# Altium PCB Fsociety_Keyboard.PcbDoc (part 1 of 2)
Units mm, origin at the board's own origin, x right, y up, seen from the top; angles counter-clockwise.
Board outline 368.7 x 110 mm, 2 copper layers (Top Layer, Bottom Layer), stack 1.601 mm thick; 249 components, 201 nets, 1088 pads, 275 vias.
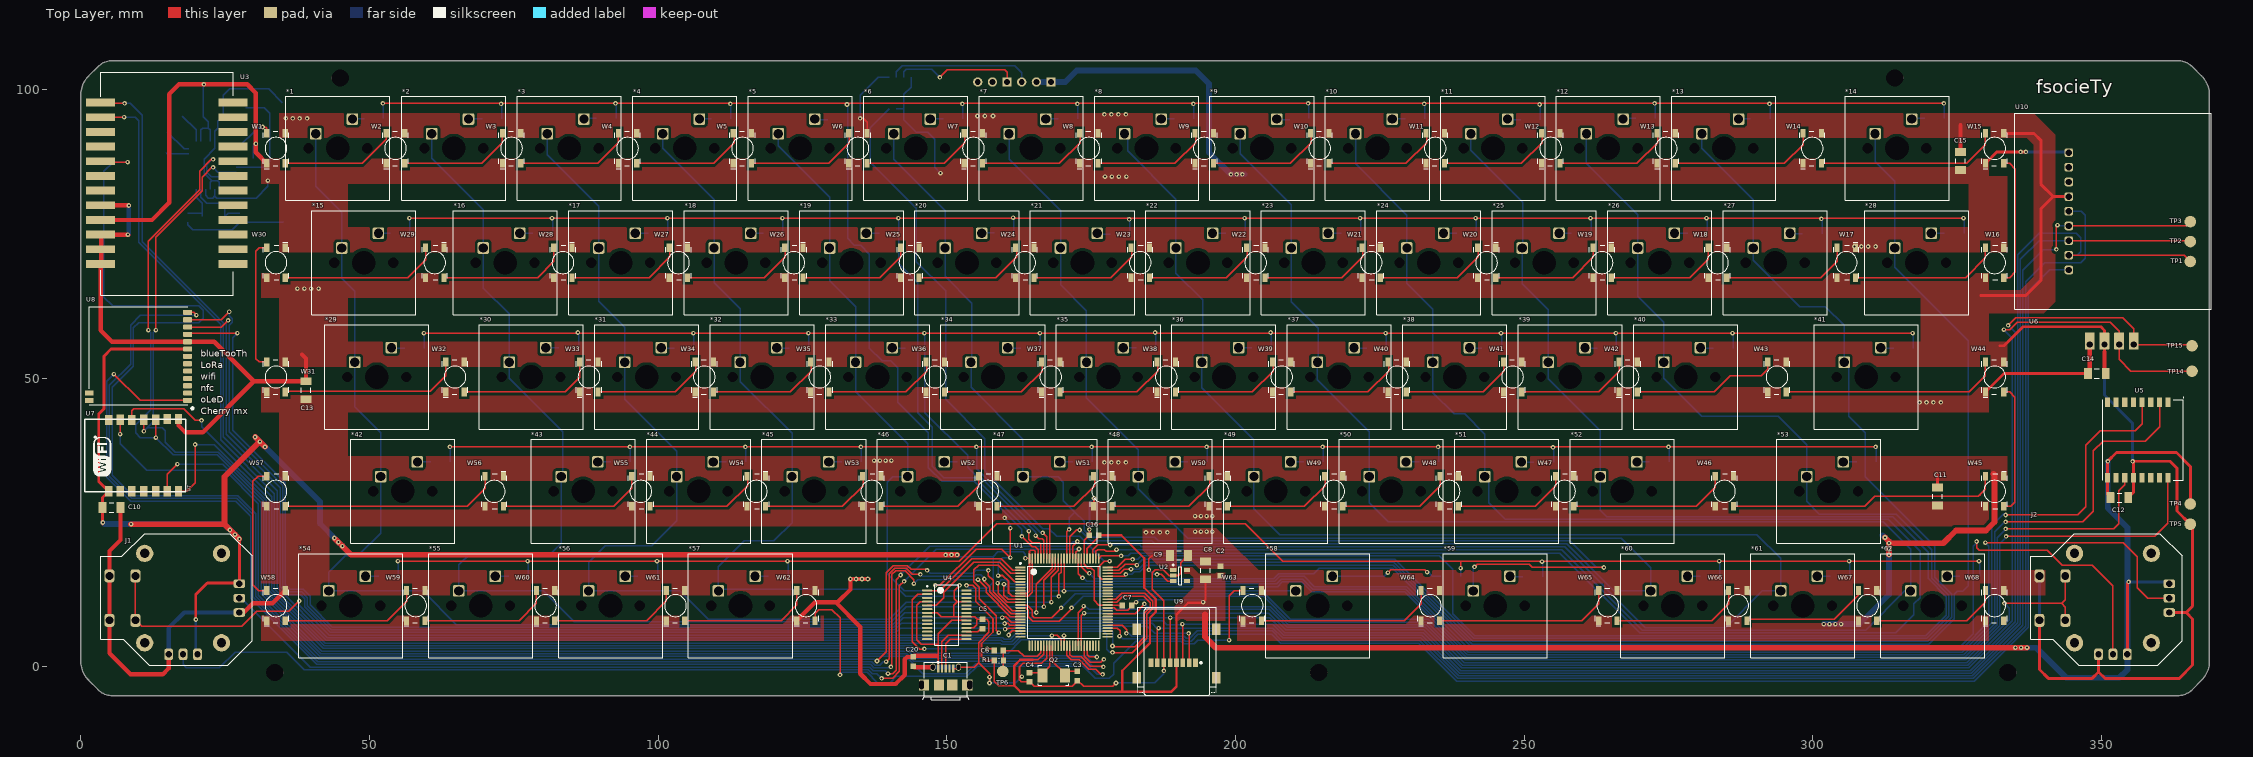
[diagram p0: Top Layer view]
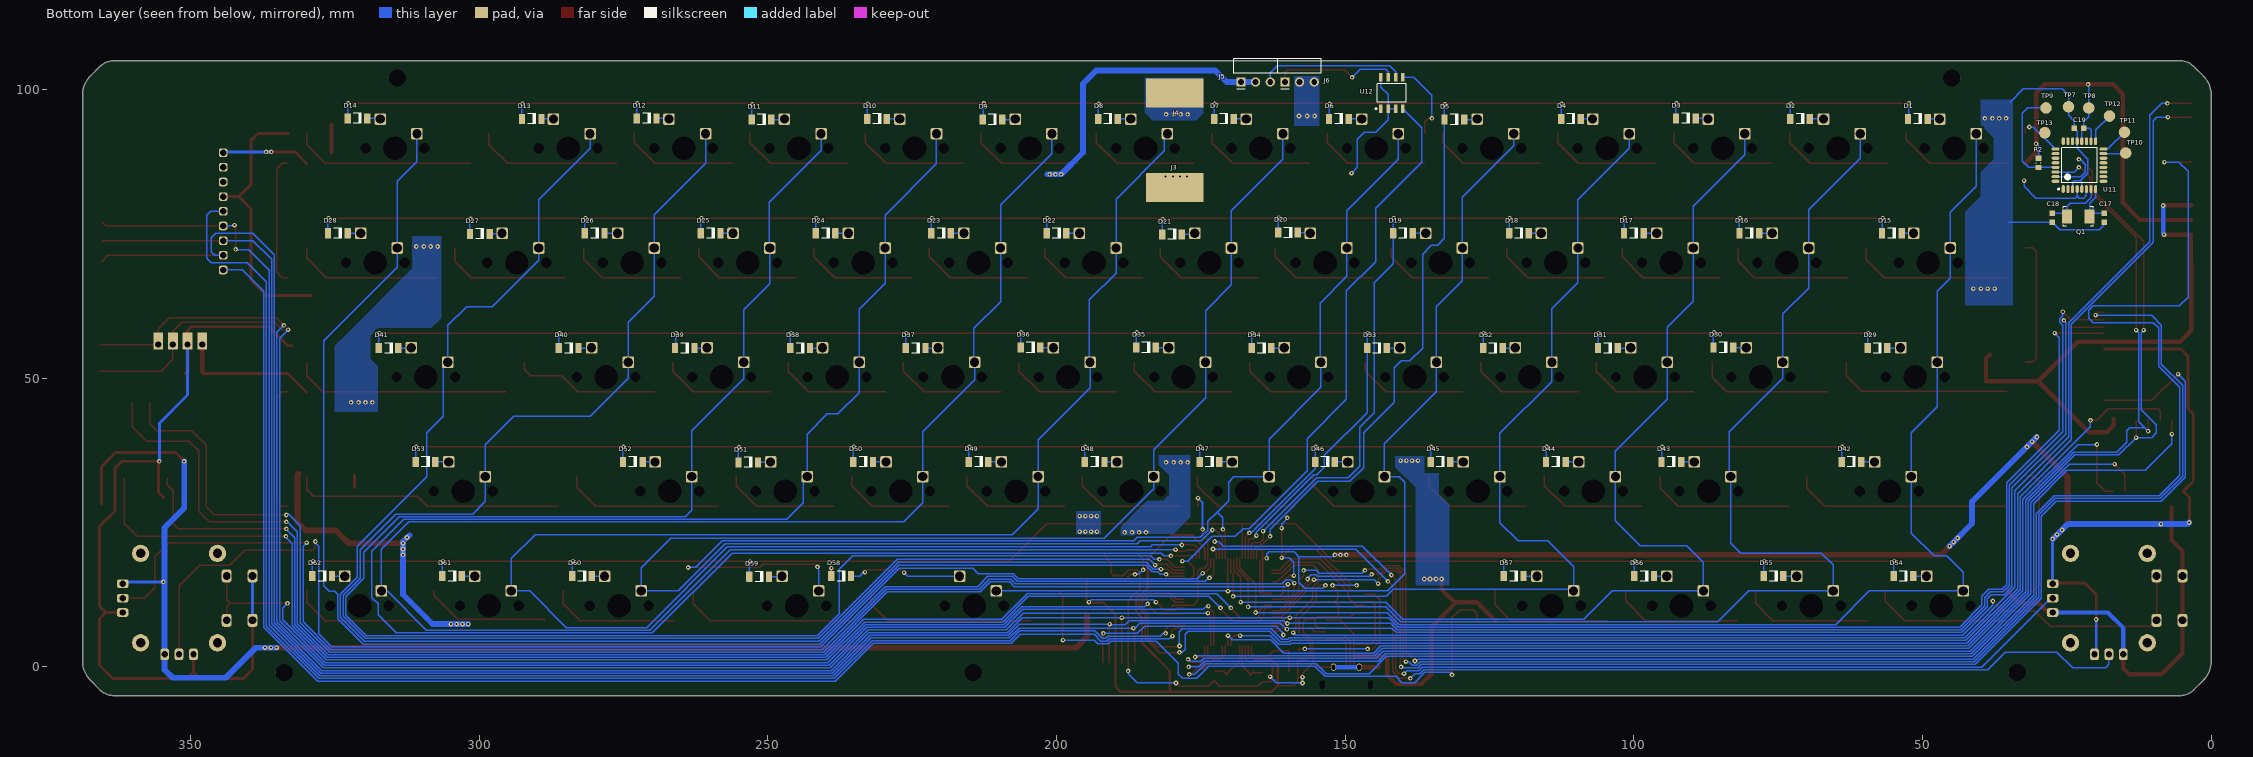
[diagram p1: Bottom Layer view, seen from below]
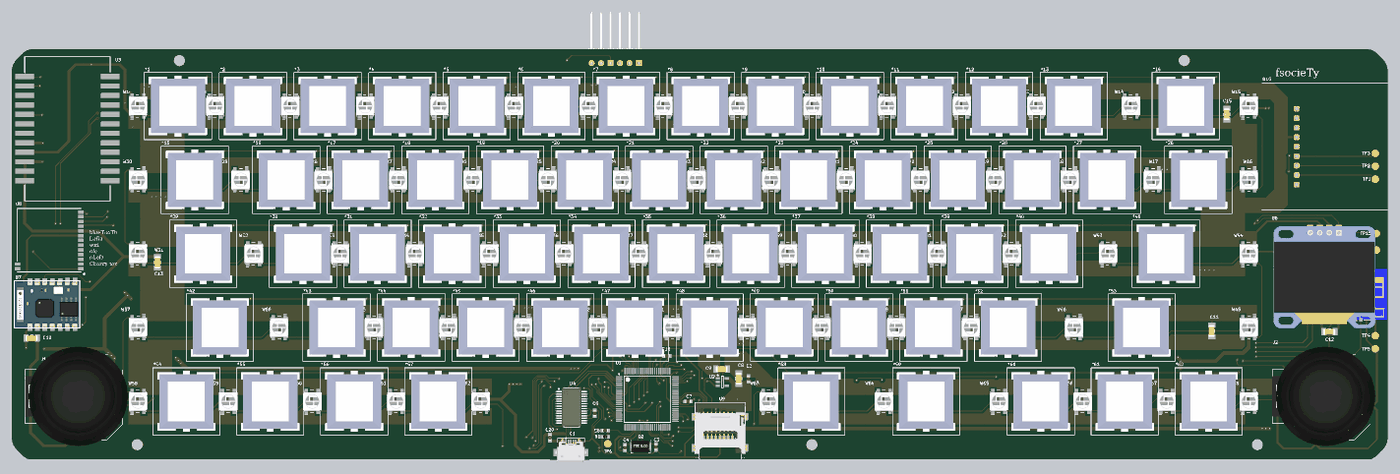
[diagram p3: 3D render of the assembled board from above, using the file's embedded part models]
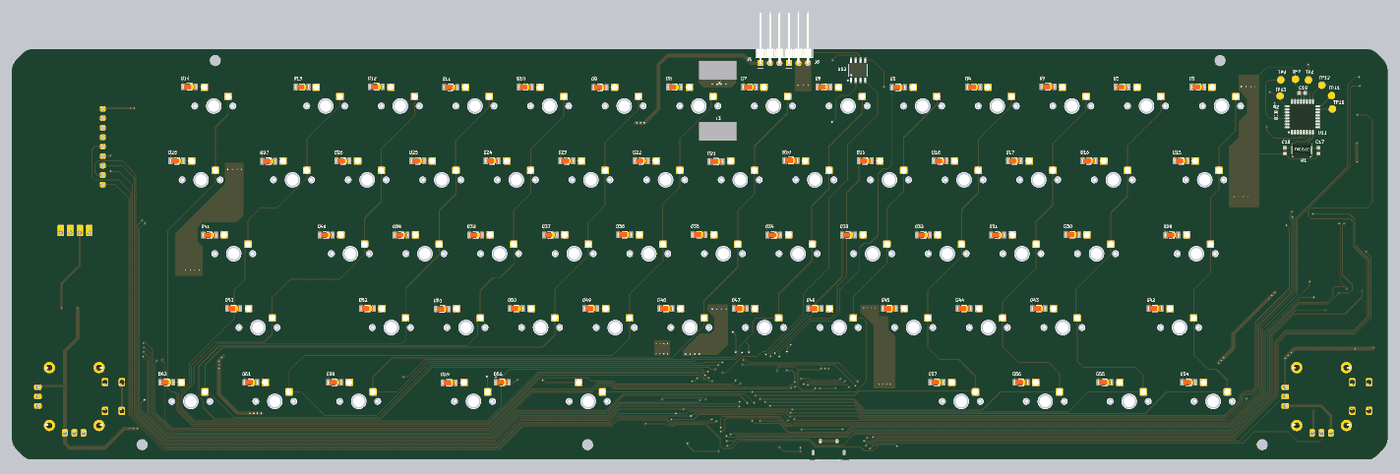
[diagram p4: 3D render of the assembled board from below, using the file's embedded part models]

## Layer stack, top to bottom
Top Solder: solder mask 0.0102, Solder Resist, Dk 3.5
Top Layer: signal copper 0.0356
Dielectric1: core 1.53, FR-4, Dk 4.8
Bottom Layer: signal copper 0.0356
Bottom Solder: solder mask 0.0102, Solder Resist, Dk 3.5

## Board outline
2.939,-3.939 1.344,-2.344 cw(c4.587,0.9) 0,0.9 0,99.1 cw(c4.587,99.1) 1.344,102.344 2.939,103.939 cw(c5.5,101.379) 5.5,105 363.2,105 cw(c363.2,101.379) 365.761,103.939 367.356,102.344 cw(c364.113,99.1) 368.7,99.1 368.7,0.9 cw(c364.113,0.9) 367.356,-2.344 365.761,-3.939 cw(c363.2,-1.379) 363.2,-5 5.5,-5 cw(c5.5,-1.379)

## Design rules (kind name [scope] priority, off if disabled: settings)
BoardOutlineClearance BoardOutlineClearance_FDC [(HasFootprint('FDC1'))] p1: gap=4
Clearance Clearance_FDC [(HasFootprint('FDC1'))] p1: gap=1.2
Clearance Clearance_Polygon [All vs InPolygon] p2: gap=0.5
Clearance [All] p3: gap=0.2
FabricationTestPointUsage TestPointUsage [All] p1: valid=0 allowmultiple=FALSE
FabricationTestpoint Testpoint [All] p1: side=3 testpointundercomponent=TRUE minsize=1.016 maxsize=2.54 preferedsize=1.524 minholesize=0 maxholesize=1.016 preferedholesize=0.813 testpointgrid=0.025 allowsidetop=TRUE allowsidebottom=TRUE usegrid=TRUE gridtolerance=0
HoleSize [All] p1: absolutevalues=TRUE maxlimit=5 minlimit=0.3 maxpercent=80.000 minpercent=20.000
MinimumAnnularRing [All] p1: minimumring=0.2
PlaneConnect [All] p1: planeconnectstyle=Direct reliefexpansion=0.508 reliefentries=4 reliefconductorwidth=0.254 reliefairgap=0.254
PolygonConnect PolygonConnect_Via [isVia] p1: connectstyle=Direct reliefconductorwidth=0.254 reliefentries=4 polygonreliefangle="90 Angle" airgapwidth=0.254
PolygonConnect [All] p2: connectstyle=Direct reliefconductorwidth=0.254 reliefentries=4 polygonreliefangle="90 Angle" airgapwidth=0.254
RoutingVias [All] p1: holewidth=0.6 width=1 viastyle="Through Hole" minholewidth=0.3 minwidth=0.6 maxholewidth=0.6 maxwidth=1.27
SilkToSolderMaskClearance SilkscreenOverComponentPads [IsPad] p1: minsilkscreentomaskgap=0.254 clearancetoexposedcopper=TRUE
SolderMaskExpansion SolderMaskExpansion_Via [ISVIA] p1: expansion=-2.515
SolderMaskExpansion [All] p2: expansion=0
Width [All] p1: maxlimit=10 minlimit=0.254 preferedwidth=0.5 minimp=50.000000 maximp=50.000000 favimp=50.000000
25 further rules are at their usual default settings.

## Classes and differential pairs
component class MK_Sumasta_LED: C17 C18 C19 Q1 R2 TP7 TP8 TP9 TP10 TP11 TP12 TP13 U11 W1 W2 W3 W4 W5 W6 W7 W8 W9 W10 W11 W12 W13 W14 W15 W16 W17 W18 W19 W20 W21 W22 W23 W24 W25 W26 W27 W28 W29 W30 W31 W32 W33 W34 W35 W36 W37 W38 W39 W40 W41 W42 W43 W44 W45 W46 W47 W48 W49 W50 W51 W52 W53 W54 W55 W56 W57 W58 W59 W60 W61 W62 W63 W64 W65 W66 W67 W68
component class MK_Sumasta_Processor: C1 C2 C3 C4 C5 C6 C7 C8 C9 C10 C11 C12 C13 C14 C15 C16 C20 J1 J2 J3 J4 J5 J6 J? Q2 R1 TP1 TP2 TP3 TP4 TP5 TP6 TP14 TP15 U1 U2 U3 U4 U5 U6 U7 U8 U9 U10 U12 U?
component class MK_Sumasta: * *1 *2 *3 *4 *5 *6 *7 *8 *9 *10 *11 *12 *13 *14 *15 *16 *17 *18 *19 *20 *21 *22 *23 *24 *25 *26 *27 *28 *29 *30 *31 *32 *33 *34 *35 *36 *37 *38 *39 *40 *41 *42 *43 *44 *45 *46 *47 *48 *49 *50 *51 *52 *53 *54 *55 *56 *57 *58 *59 *60 *61 *62 D1 D2 D3 D4 D5 D6 D7 D8 D9 D10 D11 D12 D13 D14 D15 D16 D17 D18 D19 D20 D21 D22 D23 D24 D25 D26 D27 D28 D29 D30 D31 D32 D33 D34 D35 D36 D37 D38 D39 D40 D41 D42 D43 D44 D45 D46 D47 D48 D49 D50 D51 D52 D53 D54 D55 D56 D57 D58 D59 D60 D61 D62

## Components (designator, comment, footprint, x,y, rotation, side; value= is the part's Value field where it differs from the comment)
*1 "CHERRY_MX" CHERRYMX 44.5,89.8 r0 top
*2 "CHERRY_MX" CHERRYMX 64.6,89.8 r0 top
*3 "CHERRY_MX" CHERRYMX 84.6,89.8 r0 top
*4 "CHERRY_MX" CHERRYMX 104.6,89.8 r0 top
*5 "CHERRY_MX" CHERRYMX 124.6,89.8 r0 top
*6 "CHERRY_MX" CHERRYMX 144.6,89.8 r0 top
*7 "CHERRY_MX" CHERRYMX 164.6,89.8 r0 top
*8 "CHERRY_MX" CHERRYMX 184.6,89.8 r0 top
*9 "CHERRY_MX" CHERRYMX 204.6,89.8 r0 top
*10 "CHERRY_MX" CHERRYMX 224.6,89.8 r0 top
*11 "CHERRY_MX" CHERRYMX 244.6,89.8 r0 top
*12 "CHERRY_MX" CHERRYMX 264.6,89.8 r0 top
*13 "CHERRY_MX" CHERRYMX 284.6,89.8 r0 top
*14 "CHERRY_MX" CHERRYMX 314.6,89.8 r0 top
*15 "CHERRY_MX" CHERRYMX 49,70 r0 top
*16 "CHERRY_MX" CHERRYMX 73.5,70 r0 top
*17 "CHERRY_MX" CHERRYMX 93.5,70 r0 top
*18 "CHERRY_MX" CHERRYMX 113.5,70 r0 top
*19 "CHERRY_MX" CHERRYMX 133.5,70 r0 top
*20 "CHERRY_MX" CHERRYMX 153.5,70 r0 top
*21 "CHERRY_MX" CHERRYMX 173.5,70 r0 top
*22 "CHERRY_MX" CHERRYMX 193.5,70 r0 top
*23 "CHERRY_MX" CHERRYMX 213.5,70 r0 top
*24 "CHERRY_MX" CHERRYMX 233.5,70 r0 top
*25 "CHERRY_MX" CHERRYMX 253.5,70 r0 top
*26 "CHERRY_MX" CHERRYMX 273.5,70 r0 top
*27 "CHERRY_MX" CHERRYMX 293.5,70 r0 top
*28 "CHERRY_MX" CHERRYMX 318,70 r0 top
*29 "CHERRY_MX" CHERRYMX 51.25,50.2 r0 top
*30 "CHERRY_MX" CHERRYMX 78,50.2 r0 top
*31 "CHERRY_MX" CHERRYMX 98,50.2 r0 top
*32 "CHERRY_MX" CHERRYMX 118,50.2 r0 top
*33 "CHERRY_MX" CHERRYMX 138,50.2 r0 top
*34 "CHERRY_MX" CHERRYMX 158,50.2 r0 top
*35 "CHERRY_MX" CHERRYMX 178,50.2 r0 top
*36 "CHERRY_MX" CHERRYMX 198,50.2 r0 top
*37 "CHERRY_MX" CHERRYMX 218,50.2 r0 top
*38 "CHERRY_MX" CHERRYMX 238,50.2 r0 top
*39 "CHERRY_MX" CHERRYMX 258,50.2 r0 top
*40 "CHERRY_MX" CHERRYMX 278,50.2 r0 top
*41 "CHERRY_MX" CHERRYMX 309.25,50.2 r0 top
*42 "CHERRY_MX" CHERRYMX 55.75,30.4 r0 top
*43 "CHERRY_MX" CHERRYMX 87,30.4 r0 top
*44 "CHERRY_MX" CHERRYMX 107,30.4 r0 top
*45 "CHERRY_MX" CHERRYMX 127,30.4 r0 top
*46 "CHERRY_MX" CHERRYMX 147,30.4 r0 top
*47 "CHERRY_MX" CHERRYMX 167,30.4 r0 top
*48 "CHERRY_MX" CHERRYMX 187,30.4 r0 top
*49 "CHERRY_MX" CHERRYMX 207,30.4 r0 top
*50 "CHERRY_MX" CHERRYMX 227,30.4 r0 top
*51 "CHERRY_MX" CHERRYMX 247,30.4 r0 top
*52 "CHERRY_MX" CHERRYMX 267,30.4 r0 top
*53 "CHERRY_MX" CHERRYMX 302.75,30.4 r0 top
*54 "CHERRY_MX" CHERRYMX 46.75,10.6 r0 top
*55 "CHERRY_MX" CHERRYMX 69.25,10.6 r0 top
*56 "CHERRY_MX" CHERRYMX 91.75,10.6 r0 top
*57 "CHERRY_MX" CHERRYMX 114.25,10.6 r0 top
*58 "CHERRY_MX" CHERRYMX 214.25,10.6 r0 top
*59 "CHERRY_MX" CHERRYMX 245,10.6 r0 top
*60 "CHERRY_MX" CHERRYMX 275.75,10.6 r0 top
*61 "CHERRY_MX" CHERRYMX 298.25,10.6 r0 top
*62 "CHERRY_MX" CHERRYMX 320.75,10.6 r0 top
C1 "WR-Communication Connectors 629105150921" 629105150921 149.8,-1.6 r0 top
C2 "10uF 16V" CAPC1608X08_NR 197.4,16.6 r270 top
C3 "22pf" CAPC1608X08_NR 172.6,-1.6 r90 top
C4 "22pf" CAPC1608X08_NR 164.3,-1.8 r90 top
C5 "100nf" CAPC1608X08_NR 156.2,7.4 r90 top
C6 "100nf" CAPC1608X08_NR 159,2.8 r0 top
C7 "100nf" CAPC1608X08_NR 181.2,10.6 r180 top
C8 "10uF 50V" CAPC3216X09_MW 194.8,16.7 r90 top
C9 "10uF 50V" CAPC3216X09_MW 190.2,19.3 r0 top
C10 "10uF 50V" CAPC3216X09_MW 5.3,27.6 r0 top
C11 "10uF 50V" CAPC3216X09_MW 321.6,29.5 r270 top
C12 "10uF 50V" CAPC3216X09_MW 353.1,29.3 r0 top
C13 "10uF 50V" CAPC3216X09_MW 39,47.9 r90 top
C14 "10uF 50V" CAPC3216X09_MW 349.2,50.8 r0 top
C15 "10uF 50V" CAPC3216X09_MW 325.6,87.6 r90 top
C16 "100nf" CAPC1608X08_NR 175.5,22.8 r180 top
C17 "22pf" CAPC1608X08_NR 18.5,77.8 r90 bottom
C18 "22pf" CAPC1608X08_NR 27.5,77.8 r90 bottom
C19 "100nf" CAPC1608X08_NR 22.9,93.3 r0 bottom
C20 "100nf" CAPC1608X08_NR 144.2,0.9 r90 top
D1 "1N4148" DIOMELF3515_NR_SOD80C 50.8,94.9 r0 bottom
D2 "1N4148" DIOMELF3515_NR_SOD80C 71.2,94.9 r0 bottom
D3 "1N4148" DIOMELF3515_NR_SOD80C 91,95 r0 bottom
D4 "1N4148" DIOMELF3515_NR_SOD80C 110.9,94.9 r0 bottom
D5 "1N4148" DIOMELF3515_NR_SOD80C 131.1,94.8 r0 bottom
D6 "1N4148" DIOMELF3515_NR_SOD80C 151.1,94.9 r0 bottom
D7 "1N4148" DIOMELF3515_NR_SOD80C 171,94.9 r0 bottom
D8 "1N4148" DIOMELF3515_NR_SOD80C 191.1,94.9 r0 bottom
D9 "1N4148" DIOMELF3515_NR_SOD80C 211.1,94.8 r0 bottom
D10 "1N4148" DIOMELF3515_NR_SOD80C 231.1,94.9 r0 bottom
D11 "1N4148" DIOMELF3515_NR_SOD80C 251.1,94.8 r0 bottom
D12 "1N4148" DIOMELF3515_NR_SOD80C 271,95 r0 bottom
D13 "1N4148" DIOMELF3515_NR_SOD80C 290.9,94.9 r0 bottom
D14 "1N4148" DIOMELF3515_NR_SOD80C 321.1,95 r0 bottom
D15 "1N4148" DIOMELF3515_NR_SOD80C 55.3,75.1 r0 bottom
D16 "1N4148" DIOMELF3515_NR_SOD80C 80,75.1 r0 bottom
D17 "1N4148" DIOMELF3515_NR_SOD80C 100,75.1 r0 bottom
D18 "1N4148" DIOMELF3515_NR_SOD80C 119.9,75.1 r0 bottom
D19 "1N4148" DIOMELF3515_NR_SOD80C 140,75.1 r0 bottom
D20 "1N4148" DIOMELF3515_NR_SOD80C 159.9,75.2 r0 bottom
D21 "1N4148" DIOMELF3515_NR_SOD80C 180,74.9 r0 bottom
D22 "1N4148" DIOMELF3515_NR_SOD80C 200,75.1 r0 bottom
D23 "1N4148" DIOMELF3515_NR_SOD80C 220,75.1 r0 bottom
D24 "1N4148" DIOMELF3515_NR_SOD80C 240,75.1 r0 bottom
D25 "1N4148" DIOMELF3515_NR_SOD80C 259.9,75.1 r0 bottom
D26 "1N4148" DIOMELF3515_NR_SOD80C 280,75.1 r0 bottom
D27 "1N4148" DIOMELF3515_NR_SOD80C 299.9,75 r0 bottom
D28 "1N4148" DIOMELF3515_NR_SOD80C 324.5,75.1 r0 bottom
D29 "1N4148" DIOMELF3515_NR_SOD80C 57.8,55.2 r0 bottom
D30 "1N4148" DIOMELF3515_NR_SOD80C 84.5,55.3 r0 bottom
D31 "1N4148" DIOMELF3515_NR_SOD80C 104.5,55.2 r0 bottom
D32 "1N4148" DIOMELF3515_NR_SOD80C 124.4,55.2 r0 bottom
D33 "1N4148" DIOMELF3515_NR_SOD80C 144.5,55.2 r0 bottom
D34 "1N4148" DIOMELF3515_NR_SOD80C 164.5,55.2 r0 bottom
D35 "1N4148" DIOMELF3515_NR_SOD80C 184.5,55.3 r0 bottom
D36 "1N4148" DIOMELF3515_NR_SOD80C 204.5,55.3 r0 bottom
D37 "1N4148" DIOMELF3515_NR_SOD80C 224.4,55.2 r0 bottom
D38 "1N4148" DIOMELF3515_NR_SOD80C 244.4,55.2 r0 bottom
D39 "1N4148" DIOMELF3515_NR_SOD80C 264.4,55.2 r0 bottom
D40 "1N4148" DIOMELF3515_NR_SOD80C 284.5,55.2 r0 bottom
D41 "1N4148" DIOMELF3515_NR_SOD80C 315.7,55.2 r0 bottom
D42 "1N4148" DIOMELF3515_NR_SOD80C 62.3,35.5 r0 bottom
D43 "1N4148" DIOMELF3515_NR_SOD80C 93.5,35.5 r0 bottom
D44 "1N4148" DIOMELF3515_NR_SOD80C 113.5,35.5 r0 bottom
D45 "1N4148" DIOMELF3515_NR_SOD80C 133.5,35.5 r0 bottom
D46 "1N4148" DIOMELF3515_NR_SOD80C 153.5,35.5 r0 bottom
D47 "1N4148" DIOMELF3515_NR_SOD80C 173.5,35.5 r0 bottom
D48 "1N4148" DIOMELF3515_NR_SOD80C 193.4,35.5 r0 bottom
D49 "1N4148" DIOMELF3515_NR_SOD80C 213.5,35.5 r0 bottom
D50 "1N4148" DIOMELF3515_NR_SOD80C 233.5,35.5 r0 bottom
D51 "1N4148" DIOMELF3515_NR_SOD80C 253.4,35.4 r0 bottom
D52 "1N4148" DIOMELF3515_NR_SOD80C 273.4,35.5 r0 bottom
D53 "1N4148" DIOMELF3515_NR_SOD80C 309.3,35.5 r0 bottom
D54 "1N4148" DIOMELF3515_NR_SOD80C 53.3,15.7 r0 bottom
D55 "1N4148" DIOMELF3515_NR_SOD80C 75.8,15.7 r0 bottom
D56 "1N4148" DIOMELF3515_NR_SOD80C 98.2,15.7 r0 bottom
D57 "1N4148" DIOMELF3515_NR_SOD80C 120.8,15.7 r0 bottom
D58 "1N4148" DIOMELF3515_NR_SOD80C 237.3,15.7 r0 bottom
D59 "1N4148" DIOMELF3515_NR_SOD80C 251.5,15.6 r0 bottom
D60 "1N4148" DIOMELF3515_NR_SOD80C 282.2,15.7 r0 bottom
D61 "1N4148" DIOMELF3515_NR_SOD80C 304.7,15.7 r0 bottom
D62 "1N4148" DIOMELF3515_NR_SOD80C 327.2,15.7 r0 bottom
J1 "JOYSTICK_PS2" JOYSTICK 17.7,11.9 r0 top
J2 "JOYSTICK_PS2" JOYSTICK 352,11.9 r0 top
J3 "SMD Pad" CON_SMDPAD_10X5 179.5,83 r270 bottom
J4 "SMD Pad" CON_SMDPAD_10X5 179.5,99.4 r270 bottom
J5 "BB02-HA031-KB1-100/33/D1" FCI_77315-134-03LF 165.508,101.3 r180 bottom
J6 "BB02-HA031-KB1-100/33/D1" FCI_77315-134-03LF 157.9,101.3 r180 bottom
Q1 "Crystal_txc_sumasta" Crystal_txc_sumasta 23,78 r180 bottom
Q2 "Crystal_txc_sumasta" Crystal_txc_sumasta 168.5,-1.5 r0 top
R1 "10K 1%" RESC1608X06_NR 159,1.1 r180 top
R2 "10K 1%" RESC1608X06_NR 29.9,87.3 r270 bottom
TP1 "TP" TESTPAD-2MM 365.4,70.2 r180 top
TP2 "TP" TESTPAD-2MM 365.4,73.654 r180 top
TP3 "TP" TESTPAD-2MM 365.4,77.108 r180 top
TP4 "TP" TESTPAD-2MM 365.4,28.2 r180 top
TP5 "TP" TESTPAD-2MM 365.4,24.7 r180 top
TP6 "TP" TESTPAD-2MM 159.7,-0.8 r90 top
TP7 "TP" TESTPAD-2MM 24.7,97 r90 bottom
TP8 "TP" TESTPAD-2MM 21.2,96.8 r90 bottom
TP9 "TP" TESTPAD-2MM 28.6,96.8 r90 bottom
TP10 "TP" TESTPAD-2MM 14.8,89 r90 bottom
TP11 "TP" TESTPAD-2MM 15,92.6 r90 bottom
TP12 "TP" TESTPAD-2MM 17.6,95.4 r90 bottom
TP13 "TP" TESTPAD-2MM 28.8,92.5 r90 bottom
TP14 "TP" TESTPAD-2MM 365.7,51.2 r90 top
TP15 "TP" TESTPAD-2MM 365.7,55.6 r90 top
U1 "ATmega2560-16AU" 100A_N 170.3,11.2 r0 top
U2 "TC105333ECTTR" SOT-23-CT5_N 190.4,15.8 r0 top
U3 "Bluefruit HID" "BLuefruit HID" 15,82.4 r0 top
U4 "FT232RL" SSPO28 150,9 r0 top
U5 "HM11_Sumasta" HM11_Sumasta 356.3,39.3 r270 top
U6 "OLED128X64" OLED128x64 352,44.3 r0 top
U7 "ESP8266-03" ESP8266-03 9.6,36.4 r90 top
U8 "DRF1278F" DRF1278F 10.4,53.9 r180 top
U9 "Micro SD Connector - Hinge" "Micro SD Socket" 189.8,2.3 r0 top
U10 "mfrc522" MFRC522 352,78.9 r0 top
U11 "ATmega328p" TQFP32 22.8,86.9 r90 bottom
U12 "RS485 Buffer Transceiver" SOIC127P600-8N 141.9,99.4 r90 bottom
W1 "WS2812b" DIOC500500X250_NR 33.8,89.8 r90 top
W2 "WS2812b" DIOC500500X250_NR 54.5,89.8 r90 top
W3 "WS2812b" DIOC500500X250_NR 74.6,89.8 r90 top
W4 "WS2812b" DIOC500500X250_NR 94.7,89.8 r90 top
W5 "WS2812b" DIOC500500X250_NR 114.6,89.8 r90 top
W6 "WS2812b" DIOC500500X250_NR 134.6,89.8 r90 top
W7 "WS2812b" DIOC500500X250_NR 154.6,89.8 r90 top
W8 "WS2812b" DIOC500500X250_NR 174.6,89.8 r90 top
W9 "WS2812b" DIOC500500X250_NR 194.6,89.8 r90 top
W10 "WS2812b" DIOC500500X250_NR 214.6,89.8 r90 top
W11 "WS2812b" DIOC500500X250_NR 234.6,89.8 r90 top
W12 "WS2812b" DIOC500500X250_NR 254.6,89.8 r90 top
W13 "WS2812b" DIOC500500X250_NR 274.6,89.8 r90 top
W14 "WS2812b" DIOC500500X250_NR 299.9,89.8 r90 top
W15 "WS2812b" DIOC500500X250_NR 331.5,89.8 r90 top
W16 "WS2812b" DIOC500500X250_NR 331.5,70 r270 top
W17 "WS2812b" DIOC500500X250_NR 305.8,70 r270 top
W18 "WS2812b" DIOC500500X250_NR 283.5,70 r270 top
W19 "WS2812b" DIOC500500X250_NR 263.5,70 r270 top
W20 "WS2812b" DIOC500500X250_NR 243.5,70 r270 top
W21 "WS2812b" DIOC500500X250_NR 223.5,70 r270 top
W22 "WS2812b" DIOC500500X250_NR 203.5,70 r270 top
W23 "WS2812b" DIOC500500X250_NR 183.5,70 r270 top
W24 "WS2812b" DIOC500500X250_NR 163.5,70 r270 top
W25 "WS2812b" DIOC500500X250_NR 143.6,70 r270 top
W26 "WS2812b" DIOC500500X250_NR 123.5,70 r270 top
W27 "WS2812b" DIOC500500X250_NR 103.5,70 r270 top
W28 "WS2812b" DIOC500500X250_NR 83.5,70 r270 top
W29 "WS2812b" DIOC500500X250_NR 61.3,70 r270 top
W30 "WS2812b" DIOC500500X250_NR 33.8,70 r270 top
W31 "WS2812b" DIOC500500X250_NR 33.8,50.2 r90 top
W32 "WS2812b" DIOC500500X250_NR 64.8,50.2 r90 top
W33 "WS2812b" DIOC500500X250_NR 88,50.2 r90 top
W34 "WS2812b" DIOC500500X250_NR 108,50.2 r90 top
W35 "WS2812b" DIOC500500X250_NR 128,50.2 r90 top
W36 "WS2812b" DIOC500500X250_NR 148,50.2 r90 top
W37 "WS2812b" DIOC500500X250_NR 168,50.2 r90 top
W38 "WS2812b" DIOC500500X250_NR 188,50.2 r90 top
W39 "WS2812b" DIOC500500X250_NR 208,50.2 r90 top
W40 "WS2812b" DIOC500500X250_NR 228,50.2 r90 top
W41 "WS2812b" DIOC500500X250_NR 248,50.2 r90 top
W42 "WS2812b" DIOC500500X250_NR 268,50.2 r90 top
W43 "WS2812b" DIOC500500X250_NR 293.8,50.2 r90 top
W44 "WS2812b" DIOC500500X250_NR 331.5,50.2 r90 top
W45 "WS2812b" DIOC500500X250_NR 331.5,30.4 r270 top
W46 "WS2812b" DIOC500500X250_NR 284.7,30.4 r270 top
W47 "WS2812b" DIOC500500X250_NR 257,30.4 r270 top
W48 "WS2812b" DIOC500500X250_NR 237,30.4 r270 top
W49 "WS2812b" DIOC500500X250_NR 217,30.4 r270 top
W50 "WS2812b" DIOC500500X250_NR 197,30.4 r270 top
W51 "WS2812b" DIOC500500X250_NR 177,30.4 r270 top
W52 "WS2812b" DIOC500500X250_NR 157.1,30.4 r270 top
W53 "WS2812b" DIOC500500X250_NR 137,30.4 r270 top
W54 "WS2812b" DIOC500500X250_NR 117,30.4 r270 top
W55 "WS2812b" DIOC500500X250_NR 97,30.4 r270 top
W56 "WS2812b" DIOC500500X250_NR 71.6,30.4 r270 top
W57 "WS2812b" DIOC500500X250_NR 33.8,30.4 r270 top
W58 "WS2812b" DIOC500500X250_NR 33.8,10.6 r90 top
W59 "WS2812b" DIOC500500X250_NR 58,10.6 r90 top
W60 "WS2812b" DIOC500500X250_NR 80.5,10.6 r90 top
W61 "WS2812b" DIOC500500X250_NR 103,10.6 r90 top
W62 "WS2812b" DIOC500500X250_NR 125.6,10.6 r90 top
W63 "WS2812b" DIOC500500X250_NR 202.9,10.6 r90 top
W64 "WS2812b" DIOC500500X250_NR 233.75,10.6 r90 top
W65 "WS2812b" DIOC500500X250_NR 264.5,10.6 r90 top
W66 "WS2812b" DIOC500500X250_NR 287,10.6 r90 top
W67 "WS2812b" DIOC500500X250_NR 309.5,10.6 r90 top
W68 "WS2812b" DIOC500500X250_NR 331.5,10.6 r90 top

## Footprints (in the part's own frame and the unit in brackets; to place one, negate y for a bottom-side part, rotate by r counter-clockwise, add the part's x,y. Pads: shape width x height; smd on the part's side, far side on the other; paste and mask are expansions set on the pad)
100A_N [mm] "Thin QFP, 100-Leads, Body 14x14mm, Pitch 0.5mm, IPC Medium Density"
  oval 1.8x0.3 smd: 1(-7.55,6) 2(-7.55,5.5) 3(-7.55,5) 4(-7.55,4.5) 5(-7.55,4) 6(-7.55,3.5) 7(-7.55,3) 8(-7.55,2.5) 9(-7.55,2) 10(-7.55,1.5) 11(-7.55,1) 12(-7.55,0.5) 13(-7.55,0) 14(-7.55,-0.5) 15(-7.55,-1) 16(-7.55,-1.5) 17(-7.55,-2) 18(-7.55,-2.5) 19(-7.55,-3) 20(-7.55,-3.5) 21(-7.55,-4) 22(-7.55,-4.5) 23(-7.55,-5) 24(-7.55,-5.5) 25(-7.55,-6) 51(7.55,-6) 52(7.55,-5.5) 53(7.55,-5) 54(7.55,-4.5) 55(7.55,-4) 56(7.55,-3.5) 57(7.55,-3) 58(7.55,-2.5) 59(7.55,-2) 60(7.55,-1.5) 61(7.55,-1) 62(7.55,-0.5) 63(7.55,0) 64(7.55,0.5) 65(7.55,1) 66(7.55,1.5) 67(7.55,2) 68(7.55,2.5) 69(7.55,3) 70(7.55,3.5) 71(7.55,4) 72(7.55,4.5) 73(7.55,5) 74(7.55,5.5) 75(7.55,6)
  oval 0.3x1.8 smd: 26(-6,-7.55) 27(-5.5,-7.55) 28(-5,-7.55) 29(-4.5,-7.55) 30(-4,-7.55) 31(-3.5,-7.55) 32(-3,-7.55) 33(-2.5,-7.55) 34(-2,-7.55) 35(-1.5,-7.55) 36(-1,-7.55) 37(-0.5,-7.55) 38(0,-7.55) 39(0.5,-7.55) 40(1,-7.55) 41(1.5,-7.55) 42(2,-7.55) 43(2.5,-7.55) 44(3,-7.55) 45(3.5,-7.55) 46(4,-7.55) 47(4.5,-7.55) 48(5,-7.55) 49(5.5,-7.55) 50(6,-7.55) 76(6,7.55) 77(5.5,7.55) 78(5,7.55) 79(4.5,7.55) 80(4,7.55) 81(3.5,7.55) 82(3,7.55) 83(2.5,7.55) 84(2,7.55) 85(1.5,7.55) 86(1,7.55) 87(0.5,7.55) 88(0,7.55) 89(-0.5,7.55) 90(-1,7.55) 91(-1.5,7.55) 92(-2,7.55) 93(-2.5,7.55) 94(-3,7.55) 95(-3.5,7.55) 96(-4,7.55) 97(-4.5,7.55) 98(-5,7.55) 99(-5.5,7.55) 100(-6,7.55)
  silkscreen extent -7.67,-6.25 6.25,6.82, body extent -7,-7 7,7, height 1.2
629105150921 [mm] "WR-COM_USB_Micro Type AB_Horizontal_SMT Micro Type AB Horizontal SMT - with Pegs - T&R Packaging"
  rect 0.4x1.35 smd: 1(-1.3,1.278) 2(-0.65,1.278) 3(0,1.278) 4(0.65,1.278) 5(1.3,1.278)
  oval 0.85x1.25 hole 0.65 slot 0.85 at 90 deg: Z1(-2.225,1.528) Z2(2.225,1.528)
  rect 1.8x1.9 smd: Z3(-3.76,-1.527) Z4(-1.15,-1.527) Z5(1.15,-1.527) Z6(3.76,-1.527)
  round 0 hole 0.825 slot 1.5 at 90 deg: ""(-4.175,-1.527) ""(4.175,-1.527)
  silkscreen extent -4,-4.15 4,2.47, body extent -4.3,-4.15 4.3,1.72, height 2.73
"BLuefruit HID" [mm]
  rect 5x1.37 smd: 0(-11.575,15.325) 1(-11.575,12.785) 2(-11.575,10.245) 3(-11.575,7.705) 4(-11.575,5.165) 5(-11.575,2.625) 6(-11.575,0.085) 7(-11.575,-2.455) 8(-11.575,-4.995) 9(-11.575,-7.535) 10(-11.575,-10.075) 11(-11.575,-12.615) 12(11.325,-12.615) 13(11.325,-10.075) 14(11.325,-7.535) 15(11.325,-4.995) 16(11.325,-2.455) 17(11.325,0.085) 18(11.325,2.625) 19(11.325,5.165) 20(11.325,7.705) 21(11.325,10.245) 22(11.325,12.785) 23(11.325,15.325)
  silkscreen extent -11.57,-18.05 11.35,20.6, body extent -11.5,-17.98 11.25,20.63, height 2.7
CAPC1608X08_NR [mm] "Chip Capacitor, 2-Leads, Body 1,6x0,8mm, IPC Medium Density"
  rrect5% 0.95x1 smd: 1(-0.8,0) 2(0.8,0)
  body extent -0.8,-0.4 0.8,0.4, height 0.57
CAPC3216X09_MW [mm] "Chip Capacitor, 2-Leads, Body 3,2x1,6mm, IPC Medium Density Wave"
  rrect5% 1.35x1.9 smd: 1(-1.55,0) 2(1.55,0)
  silkscreen extent -0.4,-0.8 0.4,0.8, body extent -1.6,-0.83 1.6,0.77, height 1
CHERRYMX [mm]
  rrect25% 0x0 hole 1.8: 0(-5.08,0) 0(5.08,0)
  rrect25% 0x0 hole 4.1: 0(0,0)
  rrect25% 2x2 hole 1.6: 1(-3.81,2.54) 2(2.54,5.08)
  silkscreen extent -9.02,-9.02 9.02,9.02, body extent -9,-8.98 9,9.02, height 23.25
CON_SMDPAD_10X5 [mm] "SMD PAD, 10x5mm ,IPC Medium Density"
  rrect5% 5x10 smd: 1(0,0)
Crystal_txc_sumasta [mm]
  rect 1.7x2.4 smd: 1(-1.95,0) 2(1.95,0)
  silkscreen extent -2.63,-1.73 2.63,1.73, body extent -2.5,-1.6 2.5,1.6, height 1.2
DIOC500500X250_NR [mm] "WS2812B PLCC 4, Body 5.0x5.0x.2.5mm, IPC Medium Density"
  rect 1.5x0.9 smd: 1(-2.6,1.59) 2(-2.6,-1.59) 3(2.6,-1.59) 4(2.6,1.59)
  silkscreen extent -3.5,-2.2 3,2.2, body extent -2.67,-2.48 2.68,2.47, height 1.7
DIOMELF3515_NR_SOD80C [mm] "MELF Diode, 2-Leads, Body 3,5x1,5mm, IPC Medium Density"
  rrect5% 1.1x1.75 smd: A(1.7,0) C(-1.7,0)
  silkscreen extent -0.7,-0.87 0.7,0.88, body extent -1.85,-0.8 1.85,0.8, height 1.6
DRF1278F [mm]
  rrect25% 1.5x0.9 smd: 1(-8.075,7.75) 2(-8.075,6.48) 3(-8.075,5.21) 4(-8.075,3.95) 5(-8.075,2.67) 6(-8.075,1.4) 7(-8.075,0.13) 8(-8.075,-1.14) 9(-8.075,-2.405) 10(-8.075,-3.675) 11(-8.075,-4.945) 12(-8.075,-6.215) 13(-8.075,-7.485) 14(8.925,6.48) 15(8.925,7.75)
  silkscreen extent -9.23,-8.45 8.92,9.46, body extent -8.05,-8.45 8.92,8.55, height 1.6
ESP8266-03 [mm]
  rect 1.75x1.27 smd: 1(-6.001,4.784) 2(-6.001,2.784) 3(-6.001,0.771) 4(-6.001,-1.261) 5(-6.001,-3.344) 6(-6.001,-5.351) 7(-6.001,-7.318) 8(6.521,-7.318) 9(6.496,-5.351) 10(6.394,-3.344) 11(6.394,-1.261) 12(6.344,0.771) 13(6.394,2.784) 14(6.344,4.784)
  silkscreen extent -6.08,-8.6 6.5,8.95, body extent -5.97,-8.45 6.33,8.85, height 3.41
FCI_77315-134-03LF [mm] "FCI Unshrouded header 3-pin right angle 10mm long"
  rrect5% 1.6x1.6 hole 1.02: 1(-2.54,0)
  round 1.6 hole 1.02: 2(0,0) 3(2.54,0)
  silkscreen extent -3.8,-1.3 3.8,4, body extent -3.61,-0.25 3.61,13.78, height 2.5
HM11_Sumasta [mm] "The infamous Bluetooth low Energy 4.0 from China"
  rect 1.6x0.9 smd: 1(-6.54,5.25) 2(-6.54,3.75) 3(-6.54,2.25) 4(-6.54,0.75) 5(-6.54,-0.75) 6(-6.54,-2.25) 7(-6.54,-3.75) 8(-6.54,-5.25) 9(6.54,-5.25) 10(6.54,-3.75) 11(6.54,-2.25) 12(6.54,-0.75) 13(6.54,0.75) 14(6.54,2.25) 15(6.54,3.75) 16(6.54,5.25)
  silkscreen extent -7.4,-6.1 6.95,7.95, body extent -6.76,-6.17 6.74,12.33, height 1.7
JOYSTICK [mm]
  round 3 hole 1.6: 0(-6.65,-7.75) 0(-6.65,7.75) 0(6.65,-7.75) 0(6.65,7.75)
  rrect50% 2x1.5 hole 1.1: 1(9.75,2.5) 2(9.75,0) 3(9.75,-2.5)
  rrect50% 1.5x2 hole 1.1: 4(2.5,-9.75) 5(0,-9.75) 6(-2.5,-9.75)
  rrect50% 1.7x2.25 hole 1.35: 7(-8.25,-3.85) 7(-8.25,3.85) 8(-12.75,-3.85) 8(-12.75,3.85)
  silkscreen extent -14.23,-11.65 11.98,11.17, body extent -14.22,-13.27 13.4,13.4, height 30.23
MFRC522 [mm]
  rrect50% 1.5x1.5 hole 1.1: 1(-7.65,-10.16) 2(-7.65,-7.62) 3(-7.65,-5.08) 4(-7.65,-2.54) 5(-7.65,0) 6(-7.65,2.54) 7(-7.65,5.08) 8(-7.65,7.62) 9(-7.65,10.16)
  silkscreen extent -17,-17 17,17, body extent -17,-17 17,17, height 2.7
"Micro SD Socket" [mm] "Molex50091-0801"
  rect 0.8x1.5 smd: 1(3.275,-1.575) 2(2.175,-1.575) 3(1.075,-1.575) 4(-0.025,-1.575) 5(-1.125,-1.575) 6(-2.225,-1.575) 7(-3.325,-1.575) 8(-4.425,-1.575)
  rect 1.45x2 smd: Z1(-6.875,4.175) Z2(6.875,4.175) Z3(-6.875,-4.175) Z4(6.875,-4.175)
  silkscreen extent -6.72,-7.23 6.88,7.97, body extent -7.17,-5.73 7.33,7.97, height 1.78
OLED128x64 [mm]
  rrect20% 1.7x3 hole 1.1 copper offset 0,0.6: 1(-4.015,11.525) 2(-1.475,11.525) 3(1.065,11.525) 4(3.605,11.525)
  body extent -13.85,-14.08 13.45,13.22, height 9
RESC1608X06_NR [mm] "Chip Resistor, 2-Leads, Body 1,6x0,8mm, IPC Medium Density"
  rrect5% 0.9x1 smd: 1(-0.8,0) 2(0.8,0)
  silkscreen extent -0.05,-0.4 0.05,0.4, body extent -0.85,-0.43 0.75,0.38, height 0.41
SOIC127P600-8N [mm]
  rect 1.45x0.6 smd: 1(-2.725,1.905) 2(-2.725,0.635) 3(-2.725,-0.635) 4(-2.725,-1.905) 5(2.725,-1.905) 6(2.725,-0.635) 7(2.725,0.635) 8(2.725,1.905)
  silkscreen extent -2.85,-2.5 1.6,2.88, body extent -3,-2.5 3,2.5, height 1.5
SOT-23-CT5_N [mm] "SOT23, 5-Leads, Body 2.9x1.6mm, Pitch 0.95mm, Lead Span 2.7mm, IPC Medium Density"
  rect 1.1x0.65 smd: 1(-1.2,0.95) 2(-1.2,0) 3(-1.2,-0.95) 4(1.2,-0.95) 5(1.2,0.95)
  silkscreen extent -1.32,-1.55 0.25,1.95, body extent -0.9,-1.55 0.9,1.55, height 1.45
SSPO28 [mm]
  oval 1.8x0.35 smd: 1(-3.4,4.225) 2(-3.4,3.575) 3(-3.4,2.925) 4(-3.4,2.275) 5(-3.4,1.625) 6(-3.4,0.975) 7(-3.4,0.325) 8(-3.4,-0.325) 9(-3.4,-0.975) 10(-3.4,-1.625) 11(-3.4,-2.275) 12(-3.4,-2.925) 13(-3.4,-3.575) 14(-3.4,-4.225) 15(3.4,-4.225) 16(3.4,-3.575) 17(3.4,-2.925) 18(3.4,-2.275) 19(3.4,-1.625) 20(3.4,-0.975) 21(3.4,-0.325) 22(3.4,0.325) 23(3.4,0.975) 24(3.4,1.625) 25(3.4,2.275) 26(3.4,2.925) 27(3.4,3.575) 28(3.4,4.225)
  silkscreen extent -3.52,-5.25 2.1,5.25, body extent -3.93,-5.1 3.88,5.1, height 1.9
TESTPAD-2MM [mm] "TESTPAD 2mm"
  round 2 smd paste-1: 1(0,0)
TQFP32 [mm]
  oval 1.35x0.55 smd: 1(-4.15,2.8) 2(-4.15,2) 3(-4.15,1.2) 4(-4.15,0.4) 5(-4.15,-0.4) 6(-4.15,-1.2) 7(-4.15,-2) 8(-4.15,-2.8) 17(4.15,-2.8) 18(4.15,-2) 19(4.15,-1.2) 20(4.15,-0.4) 21(4.15,0.4) 22(4.15,1.2) 23(4.15,2) 24(4.15,2.8)
  oval 0.55x1.35 smd: 9(-2.8,-4.15) 10(-2,-4.15) 11(-1.2,-4.15) 12(-0.4,-4.15) 13(0.4,-4.15) 14(1.2,-4.15) 15(2,-4.15) 16(2.8,-4.15) 25(2.8,4.15) 26(2,4.15) 27(1.2,4.15) 28(0.4,4.15) 29(-0.4,4.15) 30(-1.2,4.15) 31(-2,4.15) 32(-2.8,4.15)
  silkscreen extent -4.27,-3.05 3.05,3.75, body extent -4.5,-4.5 4.5,4.5, height 1.1

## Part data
C1: "WR-COM_USB_Micro Type AB_Horizontal_SMT"
C2 C3 C4 C5 C6 C7 C16 C17 C18 C19 C20: library part CMP-00064-A.5, "Capacitor 10nF X7R ±10% 50V 0603(1608) SMD"
C8 C9 C10 C11 C12 C13 C14 C15: library part CMP-01312-A.1, "Capacitor 10uF X5R ±20% 50V 1206(3216) SMD"
D1 D2 D3 D4 D5 D6 D7 D8 D9 D10 D11 D12 D13 D14 D15 D16 D17 D18 D19 D20 D21 D22 D23 D24 D25 D26 D27 D28 D29 D30 D31 D32 D33 D34 D35 D36 D37 D38 D39 D40 D41 D42 D43 D44 D45 D46 D47 D48 D49 D50 D51 D52 D53 D54 D55 D56 D57 D58 D59 D60 D61 D62: library part CMP-00137-A.4, "Diode 1N4148 SOD80(SMT)"
J3 J4: library part CMP-00667-A.10, "SMD PAD DIFFERENT SHAPES"
J5 J6: library part CMP-01396-A.1, "Unshrouded header 3-pin right angle"
R1 R2: library part CMP-00060-A.4, "10K  0.1W 1% 0603(1608 Metric) SMD"
TP1 TP2 TP3 TP4 TP5 TP6 TP7 TP8 TP9 TP10 TP11 TP12 TP13 TP14 TP15: library part CMP-00759-A.11, "TESTPOINT"
U1: "8-bit AVR Microcontroller, 4.5-5.5V, 16MHz, 256KB Flash, 4KB EEPROM, 8KB SRAM, 86 GPIO pins, 100-pin TQFP, Industrial Grade (-40°C to 85°C), Pb-Free"
U2: "PFM/PWM Step-Down DC/DC Controller, 1A, 3.3V, 300kHz, 5-Pin SOT-23, Industrial Temperature, Tape and Reel"
U9: library part "MicroSD Socket"
U12: library part SN75176
W1 W2 W3 W4 W5 W6 W7 W8 W9 W10 W11 W12 W13 W14 W15 W16 W17 W18 W19 W20 W21 W22 W23 W24 W25 W26 W27 W28 W29 W30 W31 W32 W33 W34 W35 W36 W37 W38 W39 W40 W41 W42 W43 W44 W45 W46 W47 W48 W49 W50 W51 W52 W53 W54 W55 W56 W57 W58 W59 W60 W61 W62 W63 W64 W65 W66 W67 W68: library part WS2812b_Sumasta, "The Infamous Chinese Chainable RGB LED"

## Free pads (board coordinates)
  oval 3x1.37 hole 3: 2(314.2,102) 3(33.6,-1) 3(44.9,102) 3(214.4,-1) 3(333.8,-1)

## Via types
v1: diameter 0.8, hole 0.35, Top Layer to Bottom Layer, tented both sides, 275 vias

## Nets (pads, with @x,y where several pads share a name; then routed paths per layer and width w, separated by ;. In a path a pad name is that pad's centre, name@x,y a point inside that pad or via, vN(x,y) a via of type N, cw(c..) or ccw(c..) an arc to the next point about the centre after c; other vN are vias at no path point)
3V3: C2.2 C7.1 C8.1 C10.1 C12.1 C16.1 J1.1 J1.4 J2.1 J2.4 R1.2 TP4.1 U1.10 U1.31 U1.61 U1.80 U1.98 U1.100 U2.5 U5.9 U7.1 U8.8 U9.4 | length 742.6
  Top Layer w0.254: v1(153.4,14.1) 154.5,14.1 155,13.6 ; v1(163.6,18.8) 164.25,18.8 U1.100@164.3,18.75 ; U1.61@177.85,10.2 178.971,10.2 179.398,9.773 181.373,9.773 181.8,10.2 C7.1@181.8,10.6 ; C12.1@351.05,29.8 C12.1@351.55,29.3
  Top Layer w0.3: 155,13.6 155,11.3 158,8.3 158,6.025 156,4.025 156,1.8 156.7,1.1 R1.2@158.2,1.1 158.2,-2.5 159,-3.3 161.7,-3.3 ; U1.10@162.75,12.7 163.9,12.7 164.3,13.1 U1.100@164.3,18.75 164.3,20 164.5,20.2 165.1,20.2 165.3,20 U1.98@165.3,18.75 ; 164.9,1.2 165.8,1.2 166.8,2.2 U1.31@166.8,3.65 ; U1.80@174.3,18.75 174.3,20.5 176.3,22.5 C16.1@176.3,22.8
  Top Layer w0.4: 164.9,1.2 162.7,1.2 161.7,0.2 161.7,-3.3 162.7,-4.3 180.4,-4.3 ; C16.1@176.3,22.8 180.2,22.8 184.2,18.8 184.2,13.7 186.181,11.719 186.181,9.481 185.2,8.5 185.2,4.1 180.4,-0.7 180.4,-4.3 ; C7.1@182,10.6 182.1,10.6 v1@182.6,11.1 ; C8.1@194.8,15.15 194.8,11.6 v1(194.4,11.2) 194.3,11.1 191.8,11.1 189.775,9.075 U9.4@189.775,0.725 189.775,-3.425 188.9,-4.3 180.4,-4.3
  Top Layer w0.5: v1@3.75,24.75 C10.1@3.75,27.6 3.75,29.333 U7.1@4.816,30.399 3.1,32.115 3.1,43.8 4,44.7 4,53.8 5.24,55.04 U8.8@18.475,55.04 ; v1(19.9,8.2) 19.9,12.5 21.9,14.5 27.35,14.5 J1.1@27.45,14.4 v1(27.45,22.15) 27.35,22.15 v1(25.8,23.7) ; C12.1@351.05,29.8 U5.9@351.05,32.76 351.05,35.55 v1(351.1,35.6) 352.6,37.1 363,37.1 365.4,34.7 TP4.1@365.4,28.2 ; J2.4@354.5,2.15 354.5,14.5 v1(354.7,14.7)
  Top Layer w1: v1(8.7,24.7) 24.9,24.7 ; v1(27.45,22.15) v1(26.7,22.9) 24.9,24.7 ; v1(30.2,39.8) v1(31,39) ; v1(31.9,38.1) v1(31,39) ; v1@44.1,22.1 v1(44.6,21.6) v1(45.3,20.9) ; v1@45.2,21 46.8,19.4 v1(149.8,19.4) v1(150.8,19.4) v1(151.8,19.4) ; 194.7,9.1 194.7,5.2 196.6,3.3 v1(335.1,3.3) v1(336.1,3.3) v1(337.1,3.3) ; 24.9,24.7 24.9,32.9 v1(31,39)
  Bottom Layer w0.254: v1(149.8,19.4) v1(150.8,19.4) v1(151.8,19.4) 152.1,19.1 158,19.1 ; v1(153.4,14.1) 153.906,13.594 156.994,13.594 158,14.6 158,19.1 ; v1(163.6,18.8) 163.6,19.5 163.2,19.9 158.8,19.9 158,19.1 ; v1(182.8,11.2) 183.227,11.627 193.973,11.627 v1(194.4,11.2)
  Bottom Layer w0.5: v1(3.8,25) 24.6,25 24.9,24.7 v1(26.7,22.9) v1(27.45,22.15) ; v1(19.9,8.2) 19.9,2.45 J1.4@20.2,2.15 ; J1.1@27.45,14.4 v1@27.45,21.9 ; v1(354.7,14.7) 361.45,14.7 J2.1@361.75,14.4
  Bottom Layer w1: v1(3.8,25) 4.1,24.7 v1(8.7,24.7) 24.65,24.7 ; 24.9,24.7 v1(27.45,22.15) ; v1(30.2,39.8) v1(31,39) v1(31.9,38.1) 41.4,28.6 41.4,24.8 v1(44.6,21.6) v1(45.3,20.9) ; v1(335.1,3.3) v1(336.1,3.3) v1(337.1,3.3) 338.7,3.3 343.9,-1.9 353.1,-1.9 354.5,-0.5 J2.4@354.5,2.15 v1@354.5,14.5 ; v1(351.1,35.6) 351.1,27.5 354.5,24.1 v1@354.5,14.5 ; v1(354.7,14.7) v1@354.5,14.5
  other v1: 43.9,22.3
C1: D1.A D2.A D3.A D4.A D5.A D6.A D7.A D8.A D9.A D10.A D11.A D12.A D13.A D14.A U1.97 | length 400.1
  Top Layer w0.254: v1@52.5,97.6 v1(272.6,97.6) v1(322.7,97.6) ; v1(163,22.6) 164.8,20.8 165.3,20.8 165.8,20.3 U1.97@165.8,18.75
  Bottom Layer w0.254: D1.A@52.4,95 v1@52.4,97.5 ; D2.A@72.9,94.9 v1@72.9,97.4 ; D3.A@92.7,95 v1@92.7,97.5 ; D4.A@112.6,94.9 v1@112.6,97.4 ; v1@132.8,97.3 D5.A@132.8,94.8 132.8,74.2 134,73 135.1,73 136.6,71.5 136.6,55.2 138.8,53 140.3,53 141.5,51.8 141.5,45.846 146.8,40.546 146.8,34.5 149.2,32.1 154.728,32.1 163,23.828 v1(163,22.6) ; D6.A@152.8,94.9 v1@152.8,97.4 ; D7.A@172.7,94.9 v1@172.7,97.4 ; D8.A@192.8,94.9 v1@192.8,97.4 ; D9.A@212.7,95 v1@212.7,97.5 ; D10.A@232.8,94.9 v1@232.8,97.4 ; D11.A@252.8,94.8 v1@252.8,97.3 ; D12.A@272.7,95 v1@272.7,97.5 ; D13.A@292.6,94.9 v1@292.6,97.4 ; v1(322.7,97.6) cw(c322.7,97.5) 322.8,97.5 D14.A@322.8,95
  other v1: 132.7,97.4 252.7,97.4 72.8,97.5 112.5,97.5 152.7,97.5 172.6,97.5 192.7,97.5 232.7,97.5 292.5,97.5 52.3,97.6 92.6,97.6 212.6,97.6
C2: D15.A D16.A D17.A D18.A D19.A D20.A D21.A D22.A D23.A D24.A D25.A D26.A D27.A D28.A U1.96 | length 374.9
  Top Layer w0.254: v1(56.9,77.7) v1(326.1,77.7) v1@326.3,77.5 ; v1(164.2,23.5) 164.2,22.1 164.8,21.5 166,21.5 166.3,21.2 U1.96@166.3,18.75
  Bottom Layer w0.254: D15.A@57,75.1 v1@57,77.6 ; D16.A@81.7,75.1 v1@81.7,77.6 ; D17.A@101.7,75.1 v1@101.7,77.6 ; D18.A@121.6,75.1 v1@121.6,77.6 ; v1@141.7,77.6 D19.A@141.7,75.1 141.7,69.8 145,66.5 145,44 147.5,41.5 147.5,34.7 149.423,32.777 154.923,32.777 v1(164.2,23.5) ; D20.A@161.6,75.2 v1@161.6,77.7 ; D21.A@181.7,74.9 v1@181.7,77.4 ; D22.A@201.7,75.1 v1@201.7,77.6 ; D23.A@221.7,75.1 v1@221.7,77.6 ; D24.A@241.7,75.1 v1@241.7,77.6 ; D25.A@261.6,75.1 v1@261.6,77.6 ; D26.A@281.7,75.1 v1@281.7,77.6 ; D27.A@301.6,75 v1@301.6,77.5 ; D28.A@326.2,75.1 v1@326.2,77.6
  other v1: 181.6,77.5 301.5,77.6 81.6,77.7 101.6,77.7 121.5,77.7 141.6,77.7 201.6,77.7 221.6,77.7 241.6,77.7 261.5,77.7 281.6,77.7 161.5,77.8
C3: D29.A D30.A D31.A D32.A D33.A D34.A D35.A D36.A D37.A D38.A D39.A D40.A D41.A U1.95 | length 336
  Top Layer w0.254: v1(59.4,57.8) v1(317.3,57.8) ; v1(165.4,22.7) 165.9,22.2 166.5,22.2 166.8,21.9 U1.95@166.8,18.75
  Bottom Layer w0.254: D29.A@59.5,55.2 v1@59.5,57.7 ; D30.A@86.2,55.3 v1@86.2,57.8 ; D31.A@106.2,55.2 v1@106.2,57.7 ; D32.A@126.1,55.2 v1@126.1,57.7 ; v1@146.2,57.7 D33.A@146.2,55.2 146.2,44 153.6,36.6 153.6,34.6 154.9,33.3 155.428,33.3 165.4,23.328 v1(165.4,22.7) ; D34.A@166.2,55.2 v1@166.2,57.7 ; D35.A@186.2,55.3 v1@186.2,57.8 ; D36.A@206.2,55.3 v1@206.2,57.8 ; D37.A@226.1,55.2 v1@226.1,57.7 ; D38.A@246.1,55.2 v1@246.1,57.7 ; D39.A@266,55.2 v1@266,57.7 ; D40.A@286.2,55.2 v1@286.2,57.7 ; D41.A@317.4,55.2 v1@317.4,57.7
  other v1: 106.1,57.8 126,57.8 146.1,57.8 166.1,57.8 226,57.8 246,57.8 265.9,57.8 286.1,57.8 86.1,57.9 186.1,57.9 206.1,57.9
C4: D42.A D43.A D44.A D45.A D46.A D47.A D48.A D49.A D50.A D51.A D52.A D53.A U1.94 | length 298.9
  Top Layer w0.254: v1(63.9,38.1) v1(95.1,38.1) v1(115.1,38.1) v1(135.1,38.1) v1(155.1,38.1) v1(175.1,38.1) v1(195,38.1) v1(215.1,38.1) v1(235.1,38.1) v1(275,38.1) v1(310.9,38.1) ; v1(166.6,23.2) 167.3,22.5 U1.94@167.3,18.75
  Bottom Layer w0.254: D42.A@64,35.5 v1@64,38 ; D43.A@95.2,35.5 v1@95.2,38 ; D44.A@115.2,35.5 v1@115.2,38 ; D45.A@135.2,35.5 v1@135.2,38 ; v1@155.2,38 D46.A@155.2,35.5 155.2,34.3 166.3,23.2 v1(166.6,23.2) ; D47.A@175.2,35.5 v1@175.2,38 ; D48.A@195.1,35.5 v1@195.1,38 ; D49.A@215.2,35.5 v1@215.2,38 ; D50.A@235.2,35.5 v1@235.2,38 ; D51.A@255.1,35.4 v1@255.1,37.9 ; D52.A@275.1,35.5 v1@275.1,38 ; D53.A@311,35.5 v1@311,38
  other v1: 255,38
C5: D54.A D55.A D56.A D57.A D58.A D59.A D60.A D61.A D62.A U1.93 | length 308
  Top Layer w0.254: v1(54.9,18.3) v1(77.4,18.3) v1(99.8,18.3) v1(122.4,18.3) 152.158,18.3 158.658,24.8 167.8,24.8 ; U1.93@167.8,18.75 167.8,24.8 ; v1(239,17.1) 239,18.2 238.9,18.3 ; v1(328.8,18.3) v1(306.3,18.3) v1(283.8,18.3) 238.9,18.3 ; 167.8,24.8 201.7,24.8 208.2,18.3 238.9,18.3
  Bottom Layer w0.254: D54.A@55,15.7 v1@55,18.2 ; D55.A@77.5,15.7 v1@77.5,18.2 ; D56.A@99.9,15.7 v1@99.9,18.2 ; D57.A@122.5,15.7 v1@122.5,18.2 ; D58.A@239,15.7 v1(239,17.1) ; D59.A@253.2,15.6 v1@253.2,18.1 ; D60.A@283.9,15.7 v1@283.9,18.2 ; D61.A@306.4,15.7 v1@306.4,18.2 ; D62.A@328.9,15.7 v1@328.9,18.2
  other v1: 253.1,18.2
DIFOUT: U1.71 U12.4 | length 106.1
  Top Layer w0.254: U1.71@177.85,15.2 176.8,15.2 176.2,15.8 176.2,17.2 177.3,18.3 v1(178.2,18.3)
  Bottom Layer w0.254: U12.4@139.995,96.675 136.7,93.38 136.7,87.4 144.7,79.4 144.7,70.2 149.8,65.1 149.8,46.3 156.6,39.5 156.6,33.985 166.658,23.927 167.673,23.927 169,22.6 173,22.6 177.3,18.3 v1(178.2,18.3)
GND: C1.5 C1.Z1 C1.Z2 C2.1 C3.1 C4.1 C5.2 C7.2 C8.2 C9.2 C10.2 C11.2 C12.2 C13.2 C14.2 C15.2 C16.2 C17.1 C18.1 C19.2 C20.1 J1.3 J1.6 J1.8 J2.3 J2.6 J2.8 J4.1 J6.2 J6.3 TP5.1 TP7.1 U1.11 U1.32 U1.62 U1.81 U1.99 U2.2 U3.7 U3.9 U3.10 U3.11 U4.7 U4.18 U4.21 U4.25 U5.12 U6.2 U7.8 U8.9 U9.6 U10.6 U11.3 U11.5 U11.21 U12.5 W1.3 W2.3 W3.3 W4.3 W5.3 W6.3 W7.3 W8.3 W9.3 W10.3 W11.3 W12.3 W13.3 W14.3 W15.3 W16.3 W17.3 W18.3 W19.3 W20.3 W21.3 W22.3 W23.3 W24.3 W25.3 W26.3 W27.3 W28.3 W29.3 W30.3 W31.3 W32.3 W33.3 W34.3 W35.3 W36.3 W37.3 W38.3 W39.3 W40.3 W41.3 W42.3 W43.3 W44.3 W45.3 W46.3 W47.3 W48.3 W49.3 W50.3 W51.3 W52.3 W53.3 W54.3 W55.3 W56.3 W57.3 W58.3 W59.3 W60.3 W61.3 W62.3 W63.3 W64.3 W65.3 W66.3 W67.3 W68.3 | length 622.2
  Top Layer w0.254: v1(135,95) 135.5,95 136.19,94.31 W6.3@136.19,92.4 ; U4.7@146.6,9.325 148.375,9.325 149.025,8.675 151.2,8.675 ; v1(148,14.1) 148.8,14.1 155.1,20.4 159.5,20.4 v1(161,18.9) ; C1.5@151.1,-0.322 151.775,-0.322 C1.Z2@152.025,-0.072 154.728,-0.072 155.5,0.7 ; v1(152.2,14.1) 151.3,13.2 151.3,11.75 151.775,11.275 ; U4.18@153.4,6.725 154.625,6.725 155.2,7.3 155.2,8.1 155.3,8.2 ; U4.25@153.4,11.275 151.775,11.275 ; v1(157.4,-2.8) v1(157.4,-1.8) 157.4,-1.2 155.5,0.7 ; v1@162.6,-1.7 v1(163,-1.7) ; C4.1@164.3,-2.6 165.1,-3.4 171.7,-3.4 172.6,-2.5 C3.1@172.6,-2.4 172.7,-2.4 173.7,-3.4 178.7,-3.4 v1(179.3,-2.8) ; U1.81@173.8,18.75 173.8,17.742 174.442,17.1 175,17.1 175.5,16.6 175.5,11.5 176.3,10.7 U1.62@177.85,10.7 179.8,10.7 C7.2@180.1,10.4 ; v1(187.6,-0.7) 187.575,-0.675 U9.6@187.575,0.725 187.575,11.425 185.6,13.4 185.6,16.3 186.1,16.8 187.5,16.8 188.5,15.8 U2.2@189.2,15.8 ; 151.2,8.675 U4.21@153.4,8.675 154.825,8.675 155.3,8.2 ; 151.2,8.675 151.2,10.7 151.775,11.275 ; 155.3,8.2 C5.2@156.2,8.2 156.9,8.2 157.3,7.8 157.3,6 155.5,4.2 155.5,0.7
  Top Layer w0.3: v1(158.9,15.8) 159.7,15.8 160.7,14.8 160.7,12.8 161.3,12.2 U1.11@162.75,12.2 164.107,12.2 164.8,12.893 U1.99@164.8,18.455 ; v1(161,18.9) v1(161,24) ; C4.1@164.3,-2.6 162.9,-2.6 162.6,-2.3 162.6,-1.7 162.6,0 163.2,0.6 166.4,0.6 167.3,1.5 U1.32@167.3,3.65 ; U1.81@173.8,18.75 173.8,21.9 C16.2@174.7,22.8 v1@174.7,23.9 ; W51.3@175.41,27.8 175.5,27.89 v1(175.5,29.2) ; U2.2@189.2,15.8 190.1,15.8 190.5,16.2 190.5,18.05 C9.2@191.75,19.3
  Top Layer w0.5: 329.1,64.3 336.9,64.3 339.5,66.9 339.5,79.28 341.66,81.44 ; 332.4,55.6 333.1,55.6 336.4,58.9 349.9,58.9 350.525,58.275 U6.2@350.525,55.825 350.525,54.525 ; W15.3@333.09,92.4 338.3,92.4 339.5,91.2 339.5,83.6 341.66,81.44 ; J2.8@339.25,8.05 339.25,-0.45 340.8,-2 348.4,-2 349.5,-0.9 ; U10.6@344.35,81.44 341.66,81.44 ; J2.6@349.35,2 J2.6@349.5,2.15 349.5,-0.9 ; C12.2@354.65,29.3 355.55,30.2 U5.12@355.55,32.76 355.55,35.45 v1(355.4,35.6) 361.9,35.6 363.1,34.4 363.1,27 TP5.1@365.4,24.7 365.8,24.3 365.8,10.5 364.7,9.4 ; J2.3@361.75,9.4 364.7,9.4 ; 349.5,-0.9 350.6,-2 363.5,-2 365.8,0.3 365.8,8.3 364.7,9.4
  Top Layer w0.75: U3.7@3.425,79.945 8.255,79.945 v1(8.3,79.9) ; C10.2@6.85,27.6 6.85,21.95 4.95,20.05 J1.8@4.95,15.75 J1.8@4.95,8.05 4.95,2.35 8.6,-1.3 14.2,-1.3 15.2,-0.3 J1.6@15.2,2.15 ; v1@8.2,74.8 v1(8.135,74.865) U3.9@3.425,74.865 3.5,74.79 3.5,69.86 U3.11@3.425,69.785 3.425,58.275 5.395,56.305 U8.9@18.475,56.305 23.095,56.305 29.95,49.45 ; U7.8@16.918,42.921 16.918,41.782 18.1,40.6 21.1,40.6 29.95,49.45 ; J1.3@27.45,9.4 28.2,9.4 29.8,11 33.19,11 W58.3@35.39,13.2 ; 38.3,54.1 39,53.4 C13.2@39,49.45 29.95,49.45 ; C20.1@144.2,0.1 144.372,-0.072 C1.Z1@147.575,-0.072 ; C15.2@325.6,89.15 325.6,93.8 ; 350.525,54.525 350.525,51.025 C14.2@350.75,50.8
  Bottom Layer w0.254: C17.1@18.5,77 18.5,76.6 19.4,75.7 26.2,75.7 C18.1@27.5,77 35,77 35.1,77.1 ; U11.5@22.4,82.75 22.4,83.9 22.7,84.2 ; U11.3@24,82.75 24,83.9 23.7,84.2 23.2,84.2 22.7,84.2 ; 34.9,97.7 32.5,100.1 25.8,100.1 24.7,99 TP7.1@24.7,97 24.7,95.5 23.7,94.5 C19.2@23.7,93.3 23.2,92.8 U11.21@23.2,91.05 23.2,89.8 21.346,87.946 21.346,85.512 22.658,84.2 22.7,84.2 ; v1(135,95) 135,99 138.125,102.125 U12.5@139.995,102.125 ; v1(148,14.1) v1(152.2,14.1) ; v1(157.4,-1.8) v1(157.4,-2.8) 161.9,-2.8 v1(163,-1.7) ; v1(179.3,-2.8) 186,-2.8 187.6,-1.2 v1(187.6,-0.7)
  Bottom Layer w0.3: v1(158.9,15.8) 158.9,18.1 159.7,18.9 v1(161,18.9) ; v1@159.9,25.8 161,24.7 v1(161,24) ; v1(174.7,23.8) 174.7,28.4 v1(175.5,29.2)
  Bottom Layer w0.5: J2.8@339.25,8.05 J2.8@339.25,15.75 ; U6.2@350.525,55.825 350.525,47.075 355.4,42.2 v1(355.4,35.6)
  Bottom Layer w0.75: v1(8.135,74.865) 8.3,75.03 v1(8.3,79.9) ; J1.6@15.2,2.15 15.2,6.7 17.9,9.4 J1.3@27.45,9.4 ; C1.Z1@147.575,-0.072 C1.Z2@152.025,-0.072
  other v1: 193,23.4 194,23.4 195,23.4 196,23.4 160,25.8 193,26.1 194,26.1 195,26.1 196,26.1 37.5,65.5 38.7,65.5 39.9,65.5 41.2,65.5 35.5,95 36.7,95 37.9,95 39.2,95 155.3,95.4 156.6,95.4 158,95.4 177.3,95.7 178.5,95.7 179.7,95.7 181,95.7
LORACS: U1.17 U8.13 | length 241.2
  Top Layer w0.254: U8.13@18.475,61.385 19.515,61.385 v1(20,60.9) ; v1(139.5,0.9) 140,1.4 140,16.142 140.939,17.081 142.961,17.081 144.042,16 v1(145.4,16) ; v1(156.5,15.2) 156.5,14.8 157.4,13.9 157.4,12.958 161.158,9.2 U1.17@162.75,9.2
  Bottom Layer w0.254: v1(20,60.9) 10.3,60.9 8.6,59.2 8.6,52.4 4.934,48.734 4.934,33.007 8.787,29.154 26.988,29.154 29.838,26.304 29.838,12.056 41.022,0.872 137,0.872 137.599,0.273 138.373,0.273 139,0.9 139.2,0.9 139.3,0.8 139.4,0.8 v1(139.5,0.9) ; v1(145.4,16) 145.7,15.7 154.8,15.7 155,15.9 155.9,15.9 156.5,15.3 v1(156.5,15.2)
LORARST: U1.18 U8.1 | length 234.5
  Top Layer w0.254: v1(5.7,50.7) 10.25,46.15 U8.1@18.475,46.15 ; v1(140.3,0) 140.5,0.2 140.5,16 141.127,16.627 142.773,16.627 144.3,15.1 v1(144.3,14.4) ; v1@155.4,14.916 v1(155.4,15.1) 156.8,13.7 156.8,12.916 161.016,8.7 U1.18@162.75,8.7
  Bottom Layer w0.254: v1(5.7,50.7) 4.48,49.48 4.48,32.819 8.599,28.7 26.8,28.7 29.384,26.116 29.384,11.868 40.834,0.418 136.782,0.418 137.381,-0.181 140.119,-0.181 v1(140.3,0) ; v1(144.3,14.4) 145,15.1 v1(155.4,15.1)
MISO: TP3.1 U1.22 U8.11 U9.7 U10.4 | length 478
  Top Layer w0.254: U8.11@18.475,58.845 24.345,58.845 v1(25.5,60) ; v1@160.2,6.4 160.3,6.4 160.6,6.7 U1.22@162.75,6.7 ; U9.7@186.475,0.725 186.475,6.625 186.55,6.7 v1(186.7,6.7) ; v1(342.2,72.3) 342.2,76.3 v1(342.4,76.5) ; U10.4@344.35,76.36 364.652,76.36 TP3.1@365.4,77.108
  Bottom Layer w0.254: v1(25.5,60) 25.2,59.7 25.2,40.3 34.5,31 34.5,13.874 35.874,12.5 38.1,12.5 38.8,11.8 38.8,10.358 43.205,5.953 141.179,5.953 141.926,6.7 159.9,6.7 v1(160.1,6.5) 160.2,6.5 161.246,7.546 163.7,7.546 163.746,7.5 185.6,7.5 v1@186.4,6.7 ; 186.2,6.9 v1@186.4,6.7 ; v1@342.3,72.2 339.9,72.2 336.407,68.707 336.407,7.225 327.62,-1.562 238.662,-1.562 232.108,4.992 208.182,4.992 206.474,6.7 191.128,6.7 191.101,6.673 186.527,6.673 186.5,6.7 v1(186.7,6.7) ; v1@342.5,76.4 342.54,76.36 U10.4@344.35,76.36 ; v1@186.4,6.7 v1(186.7,6.7) ; v1@186.4,6.7 v1(186.7,6.7)
MOSI: TP2.1 U1.21 U8.12 U9.3 U10.3 | length 476.3
  Top Layer w0.254: U8.12@18.475,60.115 24.315,60.115 v1(25.7,61.5) ; v1(160,7.5) 160.6,7.5 160.9,7.2 U1.21@162.75,7.2 ; v1(190.8,7.4) 190.875,7.325 U9.3@190.875,0.725 ; U10.3@344.35,73.82 365.234,73.82 TP2.1@365.4,73.654
  Bottom Layer w0.254: v1(25.7,61.5) 25.7,60.727 25.801,60.727 26.227,60.301 26.227,59.699 25.801,59.273 25.7,59.273 25.7,40.7 34.954,31.446 34.954,14.062 36.062,12.954 38.288,12.954 39.254,11.988 39.254,10.546 43.393,6.407 140.991,6.407 142.084,7.5 v1(160,7.5) 160.154,7.5 160.654,8 187.4,8 188.1,7.3 v1@190.9,7.3 ; v1(190.8,7.4) 206.416,7.4 208.37,5.446 232.296,5.446 238.85,-1.108 327.432,-1.108 335.953,7.413 335.953,70.553 339.22,73.82 U10.3@344.35,73.82
Net*1_2: *1.2 D1.C | length 2.1
  Bottom Layer w0.254: *1.2@47.04,94.88 47.06,94.9 D1.C@49.1,94.9
Net*2_2: *2.2 D2.C | length 2.4
  Bottom Layer w0.254: *2.2@67.14,94.88 67.16,94.9 D2.C@69.5,94.9
Net*3_2: *3.2 D3.C | length 2.2
  Bottom Layer w0.254: *3.2@87.14,94.88 87.26,95 D3.C@89.3,95
Net*4_2: *4.2 D4.C | length 2.1
  Bottom Layer w0.254: *4.2@107.14,94.88 107.16,94.9 D4.C@109.2,94.9
Net*5_2: *5.2 D5.C | length 2.3
  Bottom Layer w0.254: *5.2@127.14,94.88 127.22,94.8 D5.C@129.4,94.8
Net*6_2: *6.2 D6.C | length 2.3
  Bottom Layer w0.254: *6.2@147.14,94.88 147.16,94.9 D6.C@149.4,94.9
Net*7_2: *7.2 D7.C | length 2.2
  Bottom Layer w0.254: *7.2@167.14,94.88 167.16,94.9 D7.C@169.3,94.9
Net*8_2: *8.2 D8.C | length 2.3
  Bottom Layer w0.254: *8.2@187.14,94.88 187.16,94.9 D8.C@189.4,94.9
Net*9_2: *9.2 D9.C | length 2.3
  Bottom Layer w0.254: *9.2@207.14,94.88 207.22,94.8 D9.C@209.4,94.8
Net*10_2: *10.2 D10.C | length 2.3
  Bottom Layer w0.254: *10.2@227.14,94.88 227.16,94.9 D10.C@229.4,94.9
Net*11_2: *11.2 D11.C | length 2.3
  Bottom Layer w0.254: *11.2@247.14,94.88 247.22,94.8 D11.C@249.4,94.8
Net*12_2: *12.2 D12.C | length 2.2
  Bottom Layer w0.254: *12.2@267.14,94.88 267.26,95 D12.C@269.3,95
Net*13_2: *13.2 D13.C | length 2.1
  Bottom Layer w0.254: *13.2@287.14,94.88 287.16,94.9 D13.C@289.2,94.9
Net*14_2: *14.2 D14.C | length 2.3
  Bottom Layer w0.254: *14.2@317.14,94.88 317.26,95 D14.C@319.4,95
Net*15_2: *15.2 D15.C | length 2.1
  Bottom Layer w0.254: *15.2@51.54,75.08 51.56,75.1 D15.C@53.6,75.1
Net*16_2: *16.2 D16.C | length 2.3
  Bottom Layer w0.254: *16.2@76.04,75.08 76.06,75.1 D16.C@78.3,75.1
Net*17_2: *17.2 D17.C | length 2.3
  Bottom Layer w0.254: *17.2@96.04,75.08 96.06,75.1 D17.C@98.3,75.1
Net*18_2: *18.2 D18.C | length 2.2
  Bottom Layer w0.254: *18.2@116.04,75.08 116.06,75.1 D18.C@118.2,75.1
Net*19_2: *19.2 D19.C | length 2.3
  Bottom Layer w0.254: *19.2@136.04,75.08 136.06,75.1 D19.C@138.3,75.1
Net*20_2: *20.2 D20.C | length 2.2
  Bottom Layer w0.254: *20.2@156.04,75.08 156.16,75.2 D20.C@158.2,75.2
Net*21_2: *21.2 D21.C | length 2.3
  Bottom Layer w0.254: *21.2@176.04,75.08 176.22,74.9 D21.C@178.3,74.9
Net*22_2: *22.2 D22.C | length 2.3
  Bottom Layer w0.254: *22.2@196.04,75.08 196.06,75.1 D22.C@198.3,75.1
Net*23_2: *23.2 D23.C | length 2.3
  Bottom Layer w0.254: *23.2@216.04,75.08 216.06,75.1 D23.C@218.3,75.1
Net*24_2: *24.2 D24.C | length 2.3
  Bottom Layer w0.254: *24.2@236.04,75.08 236.06,75.1 D24.C@238.3,75.1
Net*25_2: *25.2 D25.C | length 2.2
  Bottom Layer w0.254: *25.2@256.04,75.08 256.06,75.1 D25.C@258.2,75.1
Net*26_2: *26.2 D26.C | length 2.3
  Bottom Layer w0.254: *26.2@276.04,75.08 276.06,75.1 D26.C@278.3,75.1
Net*27_2: *27.2 D27.C | length 2.2
  Bottom Layer w0.254: *27.2@296.04,75.08 296.12,75 D27.C@298.2,75
Net*28_2: *28.2 D28.C | length 2.3
  Bottom Layer w0.254: *28.2@320.54,75.08 320.56,75.1 D28.C@322.8,75.1
Net*29_2: *29.2 D29.C | length 2.3
  Bottom Layer w0.254: *29.2@53.79,55.28 53.87,55.2 D29.C@56.1,55.2
Net*30_2: *30.2 D30.C | length 2.3
  Bottom Layer w0.254: *30.2@80.54,55.28 80.56,55.3 D30.C@82.8,55.3
Net*31_2: *31.2 D31.C | length 2.3
  Bottom Layer w0.254: *31.2@100.54,55.28 100.62,55.2 D31.C@102.8,55.2
Net*32_2: *32.2 D32.C | length 2.2
  Bottom Layer w0.254: *32.2@120.54,55.28 120.62,55.2 D32.C@122.7,55.2
Net*33_2: *33.2 D33.C | length 2.3
  Bottom Layer w0.254: *33.2@140.54,55.28 140.62,55.2 D33.C@142.8,55.2
Net*34_2: *34.2 D34.C | length 2.3
  Bottom Layer w0.254: *34.2@160.54,55.28 160.62,55.2 D34.C@162.8,55.2
Net*35_2: *35.2 D35.C | length 2.3
  Bottom Layer w0.254: *35.2@180.54,55.28 180.56,55.3 D35.C@182.8,55.3
Net*36_2: *36.2 D36.C | length 2.3
  Bottom Layer w0.254: *36.2@200.54,55.28 200.56,55.3 D36.C@202.8,55.3
Net*37_2: *37.2 D37.C | length 2.2
  Bottom Layer w0.254: *37.2@220.54,55.28 220.62,55.2 D37.C@222.7,55.2
Net*38_2: *38.2 D38.C | length 2.2
  Bottom Layer w0.254: *38.2@240.54,55.28 240.62,55.2 D38.C@242.7,55.2
Net*39_2: *39.2 D39.C | length 2.2
  Bottom Layer w0.254: *39.2@260.54,55.28 260.62,55.2 D39.C@262.7,55.2
Net*40_2: *40.2 D40.C | length 2.3
  Bottom Layer w0.254: *40.2@280.54,55.28 280.62,55.2 D40.C@282.8,55.2
Net*41_2: *41.2 D41.C | length 2.2
  Bottom Layer w0.254: *41.2@311.79,55.28 311.87,55.2 D41.C@314,55.2
Net*42_2: *42.2 D42.C | length 2.3
  Bottom Layer w0.254: *42.2@58.29,35.48 58.31,35.5 D42.C@60.6,35.5
Net*43_2: *43.2 D43.C | length 2.3
  Bottom Layer w0.254: *43.2@89.54,35.48 89.56,35.5 D43.C@91.8,35.5
Net*44_2: *44.2 D44.C | length 2.3
  Bottom Layer w0.254: *44.2@109.54,35.48 109.56,35.5 D44.C@111.8,35.5
Net*45_2: *45.2 D45.C | length 2.3
  Bottom Layer w0.254: *45.2@129.54,35.48 129.56,35.5 D45.C@131.8,35.5
Net*46_2: *46.2 D46.C | length 2.3
  Bottom Layer w0.254: *46.2@149.54,35.48 149.56,35.5 D46.C@151.8,35.5
Net*47_2: *47.2 D47.C | length 2.3
  Bottom Layer w0.254: *47.2@169.54,35.48 169.56,35.5 D47.C@171.8,35.5
Net*48_2: *48.2 D48.C | length 2.2
  Bottom Layer w0.254: *48.2@189.54,35.48 189.56,35.5 D48.C@191.7,35.5
Net*49_2: *49.2 D49.C | length 2.3
  Bottom Layer w0.254: *49.2@209.54,35.48 209.56,35.5 D49.C@211.8,35.5
Net*50_2: *50.2 D50.C | length 2.3
  Bottom Layer w0.254: *50.2@229.54,35.48 229.56,35.5 D50.C@231.8,35.5
Net*51_2: *51.2 D51.C | length 2.2
  Bottom Layer w0.254: *51.2@249.54,35.48 249.62,35.4 D51.C@251.7,35.4
Net*52_2: *52.2 D52.C | length 2.2
  Bottom Layer w0.254: *52.2@269.54,35.48 269.56,35.5 D52.C@271.7,35.5
Net*53_2: *53.2 D53.C | length 2.3
  Bottom Layer w0.254: *53.2@305.29,35.48 305.31,35.5 D53.C@307.6,35.5
Net*54_2: *54.2 D54.C | length 2.3
  Bottom Layer w0.254: *54.2@49.29,15.68 49.31,15.7 D54.C@51.6,15.7
Net*55_2: *55.2 D55.C | length 2.3
  Bottom Layer w0.254: *55.2@71.79,15.68 71.81,15.7 D55.C@74.1,15.7
Net*56_2: *56.2 D56.C | length 2.2
  Bottom Layer w0.254: *56.2@94.29,15.68 94.31,15.7 D56.C@96.5,15.7
Net*57_2: *57.2 D57.C | length 2.3
  Bottom Layer w0.254: *57.2@116.79,15.68 116.81,15.7 D57.C@119.1,15.7
Net*58_2: *58.2 D58.C | length 19.8
  Top Layer w0.254: v1(226.4,16.3) 226.9,16.8 232.8,16.8 v1(233.2,16.4)
  Bottom Layer w0.254: *58.2@216.79,15.68 225.78,15.68 v1(226.4,16.3) ; v1@233.2,16.6 234.1,15.7 D58.C@235.6,15.7
Net*59_2: *59.2 D59.C | length 2.3
  Bottom Layer w0.254: *59.2@247.49,15.58 247.51,15.6 D59.C@249.8,15.6
Net*60_2: *60.2 D60.C | length 2.2
  Bottom Layer w0.254: *60.2@278.29,15.68 278.31,15.7 D60.C@280.5,15.7
Net*61_2: *61.2 D61.C | length 2.2
  Bottom Layer w0.254: *61.2@300.79,15.68 300.81,15.7 D61.C@303,15.7
Net*62_2: *62.2 D62.C | length 2.2
  Bottom Layer w0.254: *62.2@323.29,15.68 323.31,15.7 D62.C@325.5,15.7
NetC1_2: C1.2 U4.16 | length 9.4
  Top Layer w0.254: C1.2@149.15,-0.322 149.15,4.35 150.225,5.425 U4.16@153.4,5.425
NetC1_3: C1.3 U4.15 | length 8.2
  Top Layer w0.254: C1.3@149.8,-0.322 149.8,4 150.575,4.775 U4.15@153.4,4.775
NetC3_2: C3.2 Q2.2 U1.34 | length 8.5
  Top Layer w0.254: U1.34@168.3,3.65 168.3,1 170.45,-1.15 Q2.2@170.45,-1.5 171.15,-0.8 C3.2@172.6,-0.8
NetC4_2: C4.2 Q2.1 U1.33 | length 8.4
  Top Layer w0.254: C4.2@164.3,-1 Q2.1@166.05,-1 ; Q2.1@165.875,-0.825 Q2.1@166.05,-1 ; U1.33@167.8,3.65 167.8,0.1 166.55,-1.15 Q2.1@166.55,-1.5 Q2.1@166.05,-1
NetC5_1: C5.1 U4.17 | length 3.1
  Top Layer w0.254: U4.17@153.4,6.075 155.375,6.075 C5.1@156.2,6.9
NetC6_1: C6.1 U4.2 | length 25.4
  Top Layer w0.254: v1@146.2,3 145.3,3 144,4.3 144,11.6 144.975,12.575 U4.2@146.6,12.575 ; v1(157,3.1) 157.9,3.1 C6.1@158.2,2.8
  Bottom Layer w0.254: v1(146.1,3.1) v1(157,3.1) v1@157.1,3
NetC17_2: C17.2 Q1.2 U11.8 | length 7.8
  Bottom Layer w0.254: C17.2@18.5,78.6 20.95,78.6 Q1.2@21.05,78.5 ; U11.8@20,82.75 20,81.3 21.05,80.25 Q1.2@21.05,78.5 ; Q1.2@21.05,78 Q1.2@21.05,78.5
NetC18_2: C18.2 Q1.1 U11.7 | length 10.8
  Bottom Layer w0.254: U11.7@20.8,82.75 20.8,81.3 21.8,80.3 24.4,80.3 24.95,79.75 Q1.1@24.95,78 25.55,78.6 C18.2@27.5,78.6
